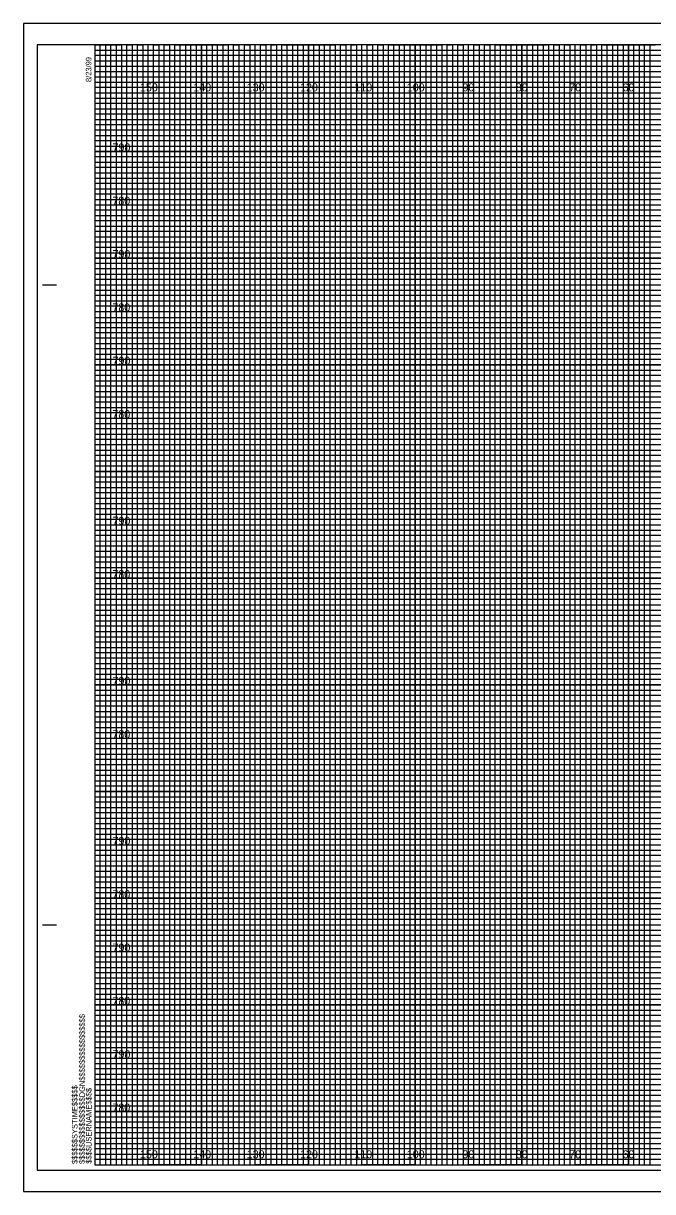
# Model space of a CAD drawing. Extents: x -13 to 323, y -5 to 214.
# Drawn here: x -13.4 to 104.5, y -5 to 214 of the extents above; entities that cross this region are included whole.
import ezdxf

# ---------------------------------------------------------------- set-up
doc = ezdxf.new("R2010")
doc.units = 0
for name, color, linetype in [('Prop XS Elevation Labels', 7, 'Continuous'), ('Prop XS Offset Labels', 7, 'Continuous'), ('Sheet Cross Section CELL', 7, 'Continuous'), ('Sheet Cross Section Grid Major CELL', 7, 'Continuous'), ('Sheet Cross Section Grid Middle CELL', 7, 'Continuous'), ('Sheet Cross Section Grid Minor 1 CELL', 7, 'Continuous'), ('Sheet Cross Section Grid Minor 2 CELL', 7, 'Continuous'), ('Sheet Cutting Line CELL', 7, 'Continuous'), ('Sheet DOT Grid CELL', 7, 'Continuous'), ('Sheet Plot Border Inside CELL', 7, 'Continuous'), ('Sheet Plot Border Outside CELL', 7, 'Continuous')]:
    doc.layers.add(name, color=color, linetype=linetype)

msp = doc.modelspace()

# ---------------------------------------------------------------- linework, layer by layer
at = {"layer": 'Sheet Cross Section CELL'}
for p, q in [((-9.8, 165), (-7.3, 165)), ((-9.7, 165), (-7.2, 165)), ((-9.8, 45), (-7.3, 45)), ((-9.7, 45), (-7.2, 45)), ((0, 0), (0, 0)), ((0, 0), (0, 0)), ((0, 0), (0, 0)), ((0, 0), (0, 0)), ((0, 0), (0, 0)), ((0, 0), (0, 0)), ((0, 0), (0, 0))]:
    msp.add_line(p, q, dxfattribs=at)
msp.add_lwpolyline([(320, 210), (0, 210), (0, 0), (320, 0)], close=True, dxfattribs=at)
at = {"layer": 'Sheet Cross Section Grid Major CELL'}
for p, q in [((10, 210), (0, 210)), ((10, 0), (10, 210)), ((30, 210), (20, 210)), ((20, 210), (20, 0)), ((30, 0), (30, 210)), ((50, 210), (40, 210)), ((40, 210), (40, 0)), ((50, 0), (50, 210)), ((70, 210), (60, 210)), ((60, 210), (60, 0)), ((70, 0), (70, 210)), ((90, 210), (80, 210)), ((80, 210), (80, 0)), ((90, 0), (90, 210)), ((110, 210), (100, 210)), ((100, 210), (100, 0)), ((20, 0), (10, 0)), ((40, 0), (30, 0)), ((60, 0), (50, 0)), ((80, 0), (70, 0)), ((100, 0), (90, 0))]:
    msp.add_line(p, q, dxfattribs=at)
for points in [[(0, 200), (320, 200), (320, 190), (0, 190)], [(0, 180), (320, 180), (320, 170), (0, 170)], [(0, 160), (320, 160), (320, 150), (0, 150)], [(0, 140), (320, 140), (320, 130), (0, 130)], [(0, 120), (320, 120), (320, 110), (0, 110)], [(0, 100), (320, 100), (320, 90), (0, 90)], [(0, 80), (320, 80), (320, 70), (0, 70)], [(0, 60), (320, 60), (320, 50), (0, 50)], [(0, 40), (320, 40), (320, 30), (0, 30)], [(0, 20), (320, 20), (320, 10), (0, 10)]]:
    msp.add_lwpolyline(points, dxfattribs=at)
at = {"layer": 'Sheet Cross Section Grid Middle CELL'}
for points in [[(0, 210), (5, 210), (5, 0), (15, 0), (15, 210), (25, 210), (25, 0), (35, 0), (35, 210), (45, 210), (45, 0), (55, 0), (55, 210), (65, 210), (65, 0), (75, 0), (75, 210), (85, 210), (85, 0), (95, 0), (95, 210), (105, 210)], [(0, 205), (275, 205)], [(0, 185), (320, 185), (320, 195), (0, 195)], [(0, 165), (320, 165), (320, 175), (0, 175)], [(0, 145), (320, 145), (320, 155), (0, 155)], [(0, 125), (320, 125), (320, 135), (0, 135)], [(0, 105), (320, 105), (320, 115), (0, 115)], [(0, 85), (320, 85), (320, 95), (0, 95)], [(0, 65), (320, 65), (320, 75), (0, 75)], [(0, 45), (320, 45), (320, 55), (0, 55)], [(0, 25), (320, 25), (320, 35), (0, 35)], [(0, 5), (320, 5), (320, 15), (0, 15)]]:
    msp.add_lwpolyline(points, dxfattribs=at)
at = {"layer": 'Sheet Cross Section Grid Minor 1 CELL'}
for p, q in [((0, 209), (260, 209)), ((260, 207.98), (0, 207.98)), ((0, 207.98), (0, 207)), ((0, 207), (260, 207)), ((260, 205.89), (0, 205.89)), ((0, 205.89), (0, 204)), ((0, 204), (320, 204))]:
    msp.add_line(p, q, dxfattribs=at)
for points in [[(0, 203), (270, 203), (320, 203), (320, 202), (0, 202)], [(0, 201), (320, 201), (320, 199), (0, 199)], [(0, 198), (320, 198), (320, 197), (0, 196.98)], [(0, 196), (320, 196), (320, 194), (0, 194)], [(0, 193), (320, 193), (320, 192), (0, 192)], [(0, 191), (320, 191), (320, 189), (0, 189)], [(0, 188), (320, 188), (320, 187), (0, 187)], [(0, 186), (320, 186), (320, 184), (0, 184)], [(0, 183), (320, 183), (320, 182), (0, 182)], [(0, 181), (320, 181), (320, 179), (0, 179)], [(0, 178), (320, 178), (320, 177), (0, 177)], [(0, 176), (320, 176), (320, 173.95), (320, 173), (320, 172), (0, 172)], [(0, 174), (320, 174), (320, 173), (0, 173)], [(0, 171), (320, 171), (320, 169), (0, 169.03)], [(0, 169.03), (320, 169), (320, 168), (0, 168)], [(0, 167), (320, 167), (320, 166), (0, 166)], [(0, 164), (320, 164), (320, 163), (0, 163)], [(0, 162), (320, 162), (320, 161), (0, 161)], [(-0.07, 158.89), (320, 158.89), (320, 157.88), (-0.07, 157.88)], [(0, 157), (320, 157), (320, 156), (0, 156)], [(0, 154), (320, 154), (320, 153), (0, 153)], [(0, 152), (320, 152), (320, 151), (0, 151)], [(0, 149), (320, 149), (320, 148), (0, 148)], [(0, 147), (320, 147), (320, 146), (0, 146)], [(0, 144), (320, 144), (320, 143), (0, 143)], [(0, 142), (320, 142), (320, 141), (0, 141)], [(0, 139), (320, 139), (319.99, 137.98), (0, 138)], [(0, 137), (320, 137), (320, 136), (0, 136)], [(0, 134), (320, 134), (320, 133), (0, 133)], [(0, 132), (320, 132), (320, 131), (0, 131)], [(0, 129), (320, 129), (320, 128), (0, 128)], [(0, 127), (320, 127), (320, 126), (0, 126)], [(0, 124), (320, 124), (320, 123), (0, 123)], [(0, 122), (320, 122), (320, 121), (0, 121)], [(0, 119), (320, 119), (320, 118), (0, 118)], [(0, 116.99), (320.07, 116.91), (320, 116), (0, 116)], [(0, 114), (320, 114), (320, 113), (0, 113)], [(0, 112), (320, 112), (320, 111), (0, 111)], [(0, 109), (320, 109), (320, 108), (0, 108)], [(0, 107), (320, 107), (320, 106), (0, 106)], [(0, 104), (320, 104), (320, 103), (0, 103)], [(0, 102), (320, 102), (320, 101), (0, 101)], [(0, 99), (320, 99), (320, 98), (0, 98)], [(0, 97), (320, 97), (320, 96), (0, 96)], [(0, 94), (320, 94), (320, 93), (0, 93)], [(0, 92), (320, 92), (320, 91), (0, 91)], [(0, 89), (320, 89), (320, 88), (0, 88)], [(0, 87), (320, 87), (320, 86), (0, 86)], [(0, 84), (320, 84), (320, 83), (0, 83)], [(0, 82), (320, 82), (320, 81), (0, 81)], [(0, 79), (320, 79), (319.99, 77.98), (0, 78)], [(0, 77), (320, 77), (320, 76), (0, 76)], [(0, 74), (320, 74), (320, 73), (0, 73)], [(0, 72), (320, 72), (320, 71), (0, 71)], [(0, 69), (320, 69), (320, 68), (0, 68)], [(0, 67), (320, 67), (320, 66), (0, 66)], [(0, 64), (320, 64), (320, 63), (0, 63)], [(0, 62), (320, 62), (320, 61), (0, 61)], [(0, 59), (320, 59), (320, 58), (0, 58)], [(0, 56.99), (320.07, 56.91), (320, 56), (0, 56)], [(0, 54), (320, 54), (320, 53), (0, 53)], [(0, 52), (320, 52), (320, 51), (0, 51)], [(0, 49), (320, 49), (320, 48), (0, 48)], [(0, 47), (320, 47), (320, 46), (0, 46)], [(0, 44), (320, 44), (320, 43), (0, 43)], [(0, 42), (320, 42), (320, 41), (0, 41)], [(0, 39), (320, 39), (320, 38), (0, 38)], [(0, 37), (320, 37), (320, 36), (0, 36)], [(0, 34), (320, 34), (320, 33), (0, 33)], [(0, 32), (320, 32), (320, 31), (0, 31)], [(0, 29), (320, 29), (320, 28), (0, 28)], [(0, 27), (320, 27), (320, 26), (0, 26)], [(0, 24), (320, 24), (320, 23), (0, 23)], [(0, 22), (320, 22), (320, 21), (0, 21)], [(0, 19), (320, 19), (320, 18), (0, 18)], [(0, 17), (320, 17), (320, 16), (0, 16)], [(0, 14), (320, 14), (320, 13), (0, 13)], [(0, 12), (320, 12), (320, 11), (0, 11)], [(0, 9), (320, 9), (320, 8), (0, 8)], [(0, 7), (320, 7), (320, 6), (0, 6)], [(0, 4), (320, 4), (320, 3), (0, 3)], [(0, 2), (320, 2), (320, 1), (0, 1)]]:
    msp.add_lwpolyline(points, dxfattribs=at)
at = {"layer": 'Sheet Cross Section Grid Minor 2 CELL'}
for points in [[(0, 0), (1, 0), (1, 210), (2, 210), (2, 0)], [(2, 0), (3, 0), (3, 210), (4, 210), (4, 0)], [(5, 0), (6, 0), (6, 210), (7, 210), (7, 0)], [(7, 0), (8, 0), (8, 210), (9, 210), (9, 0)], [(10, 0), (11, 0), (11, 210), (12, 210), (12, 0)], [(12, 0), (13, 0), (13, 210), (14, 210), (14, 0)], [(15, 0), (16, 0), (16, 210), (17, 210), (17, 0)], [(17, 0), (18, 0), (18, 210), (19, 210), (19, 0)], [(20, 0), (21, 0), (21, 210), (22, 210), (22, 0)], [(22, 0), (23, 0), (23, 210), (24, 210), (24, 0)], [(25, 0), (26, 0), (26, 210), (27, 210), (27, 0)], [(27, 0), (28, 0), (28, 210), (29, 210), (29, 0)], [(30, 0), (31, 0), (31, 210), (32, 210), (32, 0)], [(32, 0), (33, 0), (33, 210), (34, 210), (34, 0)], [(35, 0), (36, 0), (36, 210), (37, 210), (37, 0)], [(37, 0), (38, 0), (38, 210), (39, 210), (39, 0)], [(40, 0), (41, 0), (41, 210), (42, 210), (42, 0)], [(42, 0), (43, 0), (43, 210), (44, 210), (44, 0)], [(45, 0), (46, 0), (46, 210), (47, 210), (47, 0)], [(47, 0), (48, 0), (48, 210), (49, 210), (49, 0)], [(50, 0), (51, 0), (51, 210), (52, 210), (52, 0)], [(52, 0), (53, 0), (53, 210), (54, 210), (54, 0)], [(55, 0), (56, 0), (56, 210), (57, 210), (57, 0)], [(57, 0), (58, 0), (58, 210), (59, 210), (59, 0)], [(60, 0), (61, 0), (61, 210), (62, 210), (62, 0)], [(62, 0), (63, 0), (63, 210), (64, 210), (64, 0)], [(65, 0), (66, 0), (66, 210), (67, 210), (67, 0)], [(67, 0), (68, 0), (68, 210), (69, 210), (69, 0)], [(70, 0), (71, 0), (71, 210), (72, 210), (72, 0)], [(72, 0), (73, 0), (73, 210), (74, 210), (74, 0)], [(75, 0), (76, 0), (76, 210), (77, 210), (77, 0)], [(77, 0), (78, 0), (78, 210), (79, 210), (79, 0)], [(80, 0), (81, 0), (81, 210), (82, 210), (82, 0)], [(82, 0), (83, 0), (83, 210), (84, 210), (84, 0)], [(85, 0), (86, 0), (86, 210), (87, 210), (87, 0)], [(87, 0), (88, 0), (88, 210), (89, 210), (89, 0)], [(90, 0), (91, 0), (91, 210), (92, 210), (92, 0)], [(92, 0), (93, 0), (93, 210), (94, 210), (94, 0)], [(95, 0), (96, 0), (96, 210), (97, 210), (97, 0)], [(97, 0), (98, 0), (98, 210), (99, 210), (99, 0)], [(100, 0), (101, 0), (101, 210), (102, 210), (102, 0)], [(102, 0), (103, 0), (103, 210), (104, 210), (104, 0)]]:
    msp.add_lwpolyline(points, dxfattribs=at)
at = {"layer": 'Sheet Cutting Line CELL'}
for p, q in [((323.3, 214), (-13.4, 214)), ((-13.4, 214), (-13.4, -5)), ((-13.4, -5), (323.3, -5))]:
    msp.add_line(p, q, dxfattribs=at)
at = {"layer": 'Sheet DOT Grid CELL'}
for p, q in [((10, 0), (10, 210)), ((20, 0), (20, 210)), ((30, 0), (30, 210)), ((40, 0), (40, 210)), ((50, 0), (50, 210)), ((60, 0), (60, 210)), ((70, 0), (70, 210)), ((80, 0), (80, 210)), ((90, 0), (90, 210)), ((100, 0), (100, 210)), ((0, 200), (320, 200)), ((0, 190), (320, 190)), ((0, 180), (320, 180)), ((0, 170), (320, 170)), ((0, 160), (320, 160)), ((0, 150), (320, 150)), ((0, 140), (320, 140)), ((0, 130), (320, 130)), ((0, 120), (320, 120)), ((0, 110), (320, 110)), ((0, 100), (320, 100)), ((0, 90), (320, 90)), ((0, 80), (320, 80)), ((0, 70), (320, 70)), ((0, 60), (320, 60)), ((0, 50), (320, 50)), ((0, 40), (320, 40)), ((0, 30), (320, 30)), ((0, 20), (320, 20)), ((0, 10), (320, 10))]:
    msp.add_line(p, q, dxfattribs=at)
at = {"layer": 'Sheet Plot Border Inside CELL'}
msp.add_lwpolyline([(-10.8, -1), (322.4, -1), (322.4, 210), (-10.8, 210)], close=True, dxfattribs=at)
at = {"layer": 'Sheet Plot Border Outside CELL'}
msp.add_lwpolyline([(-13.4, -5), (323.3, -5), (323.3, 214), (-13.4, 214)], close=True, dxfattribs=at)

# ---------------------------------------------------------------- texts
at = {"layer": 'Prop XS Elevation Labels'}
for s, p in [('790', (3.3, 190)), ('780', (3.28, 180)), ('790', (3.3, 170)), ('780', (3.28, 160)), ('790', (3.3, 150)), ('780', (3.28, 140)), ('790', (3.3, 120)), ('780', (3.28, 110)), ('790', (3.3, 90)), ('780', (3.28, 80)), ('790', (3.3, 60)), ('780', (3.28, 50)), ('790', (3.3, 40)), ('780', (3.28, 30)), ('790', (3.3, 20)), ('780', (3.28, 10))]:
    msp.add_text(s, height=1.5, dxfattribs=at).set_placement(p)
at = {"layer": 'Prop XS Offset Labels'}
for s, p in [('150', (8.44, 201.25)), ('140', (18.44, 201.25)), ('130', (28.44, 201.25)), ('120', (38.44, 201.25)), ('110', (48.62, 201.25)), ('100', (58.44, 201.25)), ('90', (68.86, 201.25)), ('80', (78.86, 201.25)), ('70', (88.86, 201.25)), ('60', (98.86, 201.25)), ('150', (8.44, 1.25)), ('140', (18.44, 1.25)), ('130', (28.44, 1.25)), ('120', (38.44, 1.25)), ('110', (48.62, 1.25)), ('100', (58.44, 1.25)), ('90', (68.86, 1.25)), ('80', (78.86, 1.25)), ('70', (88.86, 1.25)), ('60', (98.86, 1.25))]:
    msp.add_text(s, height=1.5, dxfattribs=at).set_placement(p)
at = {"layer": 'Sheet Cross Section CELL'}
for s, p in [('8/23/99', (-0.65, 203)), ('$$$$$$$$$$$$$$$$DGN$$$$$$$$$$$$$$$$', (-1.88, 0.18)), ('$$$$$$SYSTIME$$$$$', (-3.26, 0.18)), ('$$$$USERNAME$$$$', (-0.62, 0.23))]:
    msp.add_text(s, height=1.05, rotation=90, dxfattribs=at).set_placement(p)

doc.saveas('drawing.dxf')
